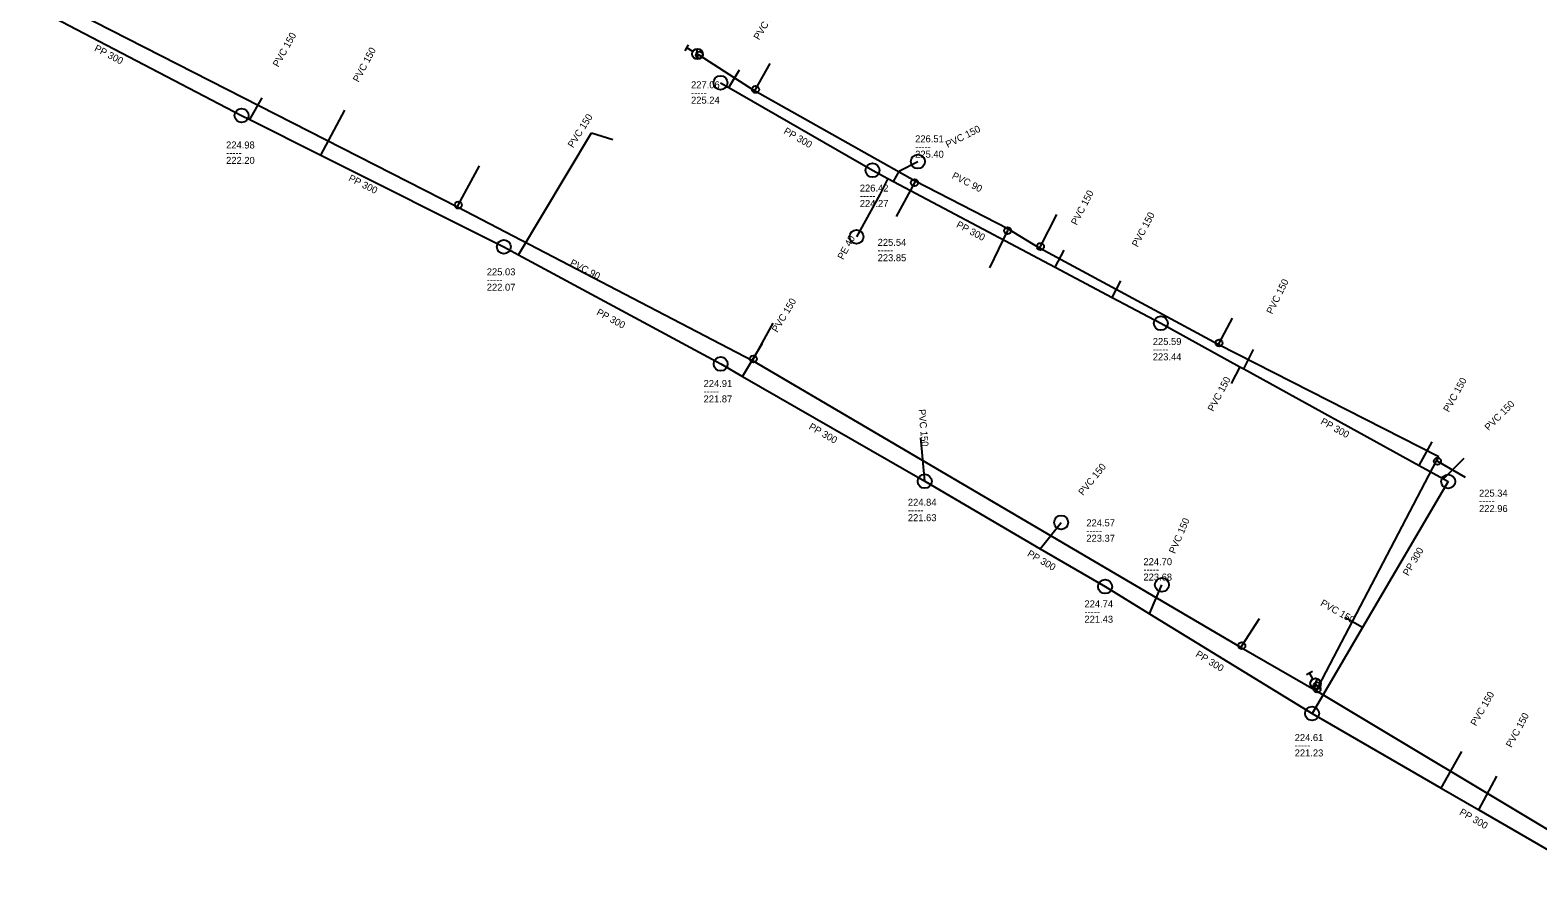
# Model space of a CAD drawing. Extents: x -771542 to -770341, y -1050442 to -1049881.
# Drawn here: x -771155.8 to -770940.3, y -1050283.5 to -1050160.7 of the extents above; entities that cross this region are included whole.
import ezdxf

# ---------------------------------------------------------------- set-up
doc = ezdxf.new("R2010")
doc.units = 0
doc.layers.add('Level 0', color=7, linetype='Continuous')

msp = doc.modelspace()

# ---------------------------------------------------------------- linework, layer by layer
at = {"layer": 'Level 0'}
for p, q in [((-771155.81, -1050154.74), (-771094.72, -1050185.98)), ((-771154.52, -1050157.84), (-771125.58, -1050172.94)), ((-771062.2, -1050163.7), (-771061.7, -1050162.83)), ((-771061.08, -1050163.76), (-771061.95, -1050163.26)), ((-771060.32, -1050164.88), (-771060.54, -1050163.4)), ((-771060.17, -1050164.3), (-771060.43, -1050164.14)), ((-771052.27, -1050169.41), (-771060.17, -1050164.3)), ((-771055.95, -1050168.93), (-771054.42, -1050166.42)), ((-771052.13, -1050169.21), (-771050.04, -1050165.48)), ((-771057.13, -1050168.25), (-771055.95, -1050168.93)), ((-771124.4, -1050173.53), (-771122.66, -1050170.4)), ((-771055.95, -1050168.93), (-771035.41, -1050180.77)), ((-771052.27, -1050169.41), (-771052.13, -1050169.21)), ((-771029.31, -1050182.31), (-771052.27, -1050169.41)), ((-771125.58, -1050172.94), (-771124.4, -1050173.53)), ((-771114.26, -1050178.61), (-771110.84, -1050172.19)), ((-771124.4, -1050173.53), (-771114.26, -1050178.61)), ((-771085.99, -1050192.85), (-771075.57, -1050175.39)), ((-771075.57, -1050175.39), (-771072.52, -1050176.37)), ((-771114.26, -1050178.61), (-771088.1, -1050191.71)), ((-771031.53, -1050180.84), (-771028.92, -1050179.52)), ((-771094.62, -1050185.75), (-771091.59, -1050180.14)), ((-771035.41, -1050180.77), (-771033.22, -1050181.93)), ((-771032.39, -1050182.37), (-771031.53, -1050180.84)), ((-771033.22, -1050181.93), (-771034.37, -1050184.22)), ((-771033.22, -1050181.93), (-771032.39, -1050182.37)), ((-771032.39, -1050182.37), (-771009.28, -1050194.64)), ((-771029.41, -1050182.54), (-771032.01, -1050187.36)), ((-771029.31, -1050182.31), (-771029.41, -1050182.54)), ((-771016.04, -1050189.15), (-771029.31, -1050182.31)), ((-771094.72, -1050185.98), (-771094.62, -1050185.75)), ((-771094.72, -1050185.98), (-771052.55, -1050207.97)), ((-771034.37, -1050184.22), (-771037.69, -1050190.28)), ((-771011.4, -1050191.67), (-771009.07, -1050187.08)), ((-771016.1, -1050189.4), (-771018.67, -1050194.7)), ((-771016.04, -1050189.15), (-771016.1, -1050189.4)), ((-771011.53, -1050191.89), (-771016.04, -1050189.15)), ((-771088.1, -1050191.71), (-771085.99, -1050192.85)), ((-771011.53, -1050191.89), (-771011.4, -1050191.67)), ((-770985.99, -1050205.7), (-771011.53, -1050191.89)), ((-771009.28, -1050194.64), (-771008.02, -1050192.21)), ((-771085.99, -1050192.85), (-771057.11, -1050208.46)), ((-771009.28, -1050194.64), (-771001.16, -1050198.95)), ((-771001.16, -1050198.95), (-770999.91, -1050196.56)), ((-771001.16, -1050198.95), (-770994.19, -1050202.65)), ((-771052.44, -1050207.75), (-771049.62, -1050202.61)), ((-770994.19, -1050202.65), (-770982.88, -1050208.86)), ((-770985.87, -1050205.47), (-770983.95, -1050201.9)), ((-771054, -1050210.25), (-771051.15, -1050205.49)), ((-770985.99, -1050205.7), (-770985.87, -1050205.47)), ((-770954.48, -1050221.74), (-770985.99, -1050205.7)), ((-770982.34, -1050209.17), (-770980.95, -1050206.38)), ((-771057.11, -1050208.46), (-771054, -1050210.25)), ((-771052.55, -1050207.97), (-771052.44, -1050207.75)), ((-771052.55, -1050207.97), (-770982.7, -1050248.99)), ((-770982.88, -1050208.86), (-770984.15, -1050211.26)), ((-770982.88, -1050208.86), (-770982.34, -1050209.17)), ((-770982.34, -1050209.17), (-770957.29, -1050222.96)), ((-771054, -1050210.25), (-771027.95, -1050225.24)), ((-771027.95, -1050225.24), (-771028.49, -1050219.03)), ((-770957.29, -1050222.96), (-770955.41, -1050219.58)), ((-770971.65, -1050254.57), (-770954.77, -1050222.29)), ((-770954.77, -1050222.29), (-770954.48, -1050221.74)), ((-770954.77, -1050222.29), (-770954.65, -1050222.36)), ((-770954.65, -1050222.36), (-770950.68, -1050224.65)), ((-770953.8, -1050224.88), (-770950.86, -1050221.91)), ((-770957.29, -1050222.96), (-770953.8, -1050224.88)), ((-771027.95, -1050225.24), (-771011.46, -1050234.87)), ((-770953.11, -1050225.26), (-770965.37, -1050246.14)), ((-770953.8, -1050224.88), (-770953.11, -1050225.26)), ((-771011.46, -1050234.87), (-771008.44, -1050231.12)), ((-771011.46, -1050234.87), (-771002.16, -1050240.3)), ((-771002.16, -1050240.3), (-770995.83, -1050244.18)), ((-770995.83, -1050244.18), (-770994.03, -1050240.04)), ((-770995.83, -1050244.18), (-770972.58, -1050258.43)), ((-770982.62, -1050248.75), (-770980.11, -1050244.86)), ((-770965.37, -1050246.14), (-770972.58, -1050258.43)), ((-770965.37, -1050246.14), (-770967.88, -1050244.71)), ((-770982.7, -1050248.99), (-770982.62, -1050248.75)), ((-770982.7, -1050248.99), (-770971.95, -1050255.18)), ((-770973.39, -1050252.88), (-770972.52, -1050252.38)), ((-770972.45, -1050253.5), (-770972.95, -1050252.63)), ((-770972.36, -1050254.84), (-770971.8, -1050253.45)), ((-770972.08, -1050254.15), (-770971.86, -1050254.46)), ((-770971.95, -1050255.18), (-770971.85, -1050254.95)), ((-770971.86, -1050254.46), (-770971.65, -1050254.57)), ((-770971.85, -1050254.95), (-770971.65, -1050254.57)), ((-770971.95, -1050255.18), (-770932.14, -1050279.1)), ((-770972.58, -1050258.43), (-770954.14, -1050269.1)), ((-770954.14, -1050269.1), (-770951.15, -1050263.86)), ((-770948.76, -1050272.21), (-770946.18, -1050267.4)), ((-770954.14, -1050269.1), (-770948.76, -1050272.21)), ((-770948.76, -1050272.21), (-770929.23, -1050283.51))]:
    msp.add_line(p, q, dxfattribs=at)
for centre, radius in [((-771060.43, -1050164.14), 0.75), ((-771060.17, -1050164.3), 0.5), ((-771057.13, -1050168.25), 1), ((-771052.13, -1050169.21), 0.5), ((-771125.58, -1050172.94), 1), ((-771028.92, -1050179.52), 1), ((-771035.41, -1050180.77), 1), ((-771029.41, -1050182.54), 0.5), ((-771094.62, -1050185.75), 0.5), ((-771037.69, -1050190.28), 1), ((-771016.1, -1050189.4), 0.5), ((-771088.1, -1050191.71), 1), ((-771011.4, -1050191.67), 0.5), ((-770994.19, -1050202.65), 1), ((-770985.87, -1050205.47), 0.5), ((-771057.11, -1050208.46), 1), ((-771052.44, -1050207.75), 0.5), ((-770954.65, -1050222.36), 0.5), ((-771027.95, -1050225.24), 1), ((-770953.11, -1050225.26), 1), ((-771008.44, -1050231.12), 1), ((-771002.16, -1050240.3), 1), ((-770994.03, -1050240.04), 1), ((-770982.62, -1050248.75), 0.5), ((-770972.08, -1050254.15), 0.75), ((-770971.86, -1050254.46), 0.5), ((-770971.85, -1050254.95), 0.5), ((-770972.58, -1050258.43), 1)]:
    msp.add_circle(centre, radius, dxfattribs=at)

# ---------------------------------------------------------------- texts
for s, rotation, p in [('PVC 150', 58.635, (-771051.63, -1050162.22)), ('PVC 150', 60.93, (-771120.33, -1050166.1)), ('PP 300', 332.446, (-771146.73, -1050163.64)), ('PVC 150', 61.955, (-771108.86, -1050168.26)), ('PVC 150', 57.869, (-771078.2, -1050177.64)), ('PP 300', 330.039, (-771048.2, -1050175.45)), ('PVC 150', 26.828, (-771024.65, -1050177.59)), ('PP 300', 333.39, (-771110.4, -1050182.22)), ('PVC 90', 333.118, (-771024.15, -1050181.86)), ('PVC 150', 62.592, (-771006.21, -1050188.7)), ('PP 300', 332.034, (-771023.52, -1050188.85)), ('PVC 150', 62.39, (-770997.51, -1050191.83)), ('PE 40', 61.284, (-771039.61, -1050193.63)), ('PVC 90', 332.46, (-771078.75, -1050194.31)), ('PVC 150', 63.517, (-770978.27, -1050201.42)), ('PP 300', 331.608, (-771074.95, -1050201.37)), ('PVC 150', 59.089, (-771049.01, -1050204.04)), ('PVC 150', 62.114, (-770986.68, -1050215.35)), ('PVC 150', 60.917, (-770953.02, -1050215.44)), ('PVC 150', 45.291, (-770947.32, -1050218.07)), ('PVC 150', 274.97, (-771028.84, -1050214.97)), ('PP 300', 331.167, (-770971.46, -1050216.99)), ('PP 300', 330.083, (-771044.61, -1050217.71)), ('PVC 150', 51.154, (-771005.31, -1050227.35)), ('PVC 150', 66.501, (-770992.18, -1050235.67)), ('PP 300', 329.721, (-771013.38, -1050235.86)), ('PP 300', 59.602, (-770958.81, -1050238.85)), ('PVC 150', 330.329, (-770971.48, -1050242.94)), ('PP 300', 328.496, (-770989.32, -1050250.22)), ('PVC 150', 60.29, (-770949.14, -1050260.31)), ('PVC 150', 61.792, (-770944.06, -1050263.4)), ('PP 300', 329.946, (-770951.61, -1050272.82))]:
    msp.add_text(s, height=1, rotation=rotation, dxfattribs=at).set_placement(p)
for s, p in [('227.06', (-771061.34, -1050169.04)), ('-----', (-771061.34, -1050170.14)), ('225.24', (-771061.34, -1050171.24)), ('224.98', (-771127.8, -1050177.65)), ('226.51', (-771029.31, -1050176.77)), ('-----', (-771127.8, -1050178.75)), ('222.20', (-771127.8, -1050179.85)), ('-----', (-771029.31, -1050177.87)), ('225.40', (-771029.31, -1050178.97)), ('226.42', (-771037.22, -1050183.81)), ('-----', (-771037.22, -1050184.91)), ('224.27', (-771037.22, -1050186.01)), ('-----', (-771034.67, -1050192.67)), ('225.54', (-771034.67, -1050191.57)), ('223.85', (-771034.67, -1050193.77)), ('-----', (-771090.54, -1050196.89)), ('225.03', (-771090.54, -1050195.79)), ('222.07', (-771090.54, -1050197.99)), ('225.59', (-770995.34, -1050205.74)), ('-----', (-770995.34, -1050206.84)), ('223.44', (-770995.34, -1050207.94)), ('224.91', (-771059.55, -1050211.76)), ('-----', (-771059.55, -1050212.86)), ('221.87', (-771059.55, -1050213.96)), ('225.34', (-770948.71, -1050227.43)), ('224.84', (-771030.35, -1050228.74)), ('-----', (-770948.71, -1050228.53)), ('222.96', (-770948.71, -1050229.63)), ('-----', (-771030.35, -1050229.84)), ('221.63', (-771030.35, -1050230.94)), ('224.57', (-771004.84, -1050231.68)), ('-----', (-771004.84, -1050232.78)), ('223.37', (-771004.84, -1050233.88)), ('224.70', (-770996.68, -1050237.23)), ('-----', (-770996.68, -1050238.33)), ('223.68', (-770996.68, -1050239.43)), ('-----', (-771005.11, -1050244.36)), ('224.74', (-771005.11, -1050243.26)), ('221.43', (-771005.11, -1050245.46)), ('224.61', (-770975.06, -1050262.38)), ('-----', (-770975.06, -1050263.48)), ('221.23', (-770975.06, -1050264.58))]:
    msp.add_text(s, height=1, dxfattribs=at).set_placement(p)

doc.saveas('drawing.dxf')
